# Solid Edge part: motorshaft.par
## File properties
Author: Robert a Rhodes jr
Template: NORMENG.PAR
Last saved by: CADCIM
Revision: 7
Application: Solid Edge
Accuracy: 0.99
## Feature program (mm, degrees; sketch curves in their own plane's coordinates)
sketch for "unnamed Protrusion 1" plane through (0, 0, 0) normal (0, -1, 0) x-axis (1, 0, 0)
  circle centre (0, 0) radius 18.415
extrude "unnamed Protrusion 1" add finite 609.6 along -normal
sketch for "unnamed RevolvedCutout 1" plane through (0, 0, 0) normal (0, 0, 1) x-axis (1, 0, 0)
  line (18.415, 592.328) -> (18.415, 596.9)
  line (18.415, 596.9) -> (14.1403, 596.9)
  line (14.1403, 596.9) -> (14.1403, 592.328)
  line (14.1403, 592.328) -> (18.415, 592.328)
revolve "unnamed RevolvedCutout 1" cut finite 360 deg about sketch line (-1.0997, 601.5888) -> (-1.0997, 629.75)
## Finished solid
Body 1: solid body, 7 faces, 6 edges, 0 vertices.
  Faces by surface: plane 4, cylinder 3
  Edges by curve: circle 6
Bounding box of the edges (mm): 36.830 x 609.600 x 36.830, from (-18.415, 0, -18.415) to (18.415, 609.6, 18.415).
Cylindrical faces by radius (mm): R15.24 x1, R18.415 x2
Planar faces by outward normal: +y 2, -y 2
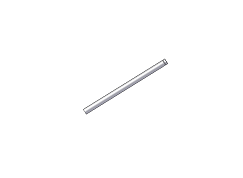
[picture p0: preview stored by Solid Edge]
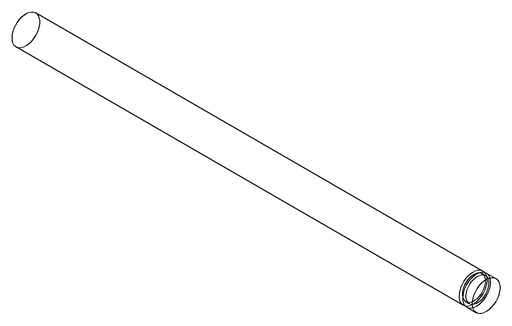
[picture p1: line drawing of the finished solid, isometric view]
